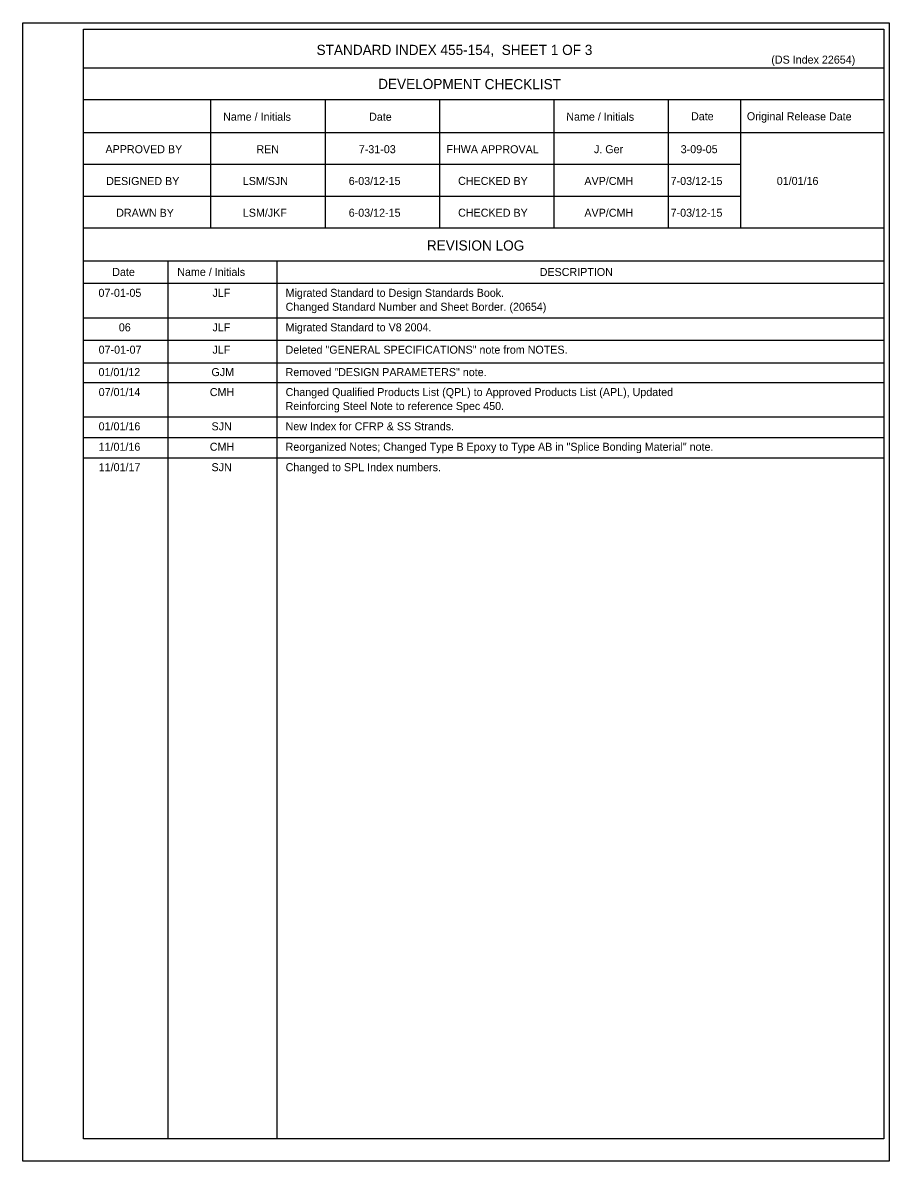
# Model space of a CAD drawing. Extents: x 120517.2 to 120592, y 120519.3 to 120603.1.
# Drawn here: x 120570.2 to 120592.01, y 120568.69 to 120597.36 of the extents above; entities that cross this region are included whole.
import ezdxf

# ---------------------------------------------------------------- set-up
doc = ezdxf.new("R2010")
doc.units = 0
for name, color, linetype in [('AdhocPoint_dp', 7, 'Continuous'), ('Border', 7, 'Continuous'), ('PlotBorder_dp', 7, 'Continuous'), ('SheetBorder_dp', 7, 'Continuous')]:
    doc.layers.add(name, color=color, linetype=linetype)

msp = doc.modelspace()

# ---------------------------------------------------------------- linework, layer by layer
at = {"layer": 'Border'}
for p, q in [((120591.874, 120596.217), (120571.727, 120596.217)), ((120591.874, 120595.417), (120571.727, 120595.417)), ((120574.927, 120595.417), (120574.927, 120592.189)), ((120577.807, 120595.417), (120577.807, 120592.189)), ((120580.687, 120595.417), (120580.687, 120592.189)), ((120583.567, 120595.417), (120583.567, 120592.189)), ((120586.447, 120595.417), (120586.447, 120592.189)), ((120588.262, 120595.417), (120588.262, 120592.189)), ((120591.874, 120594.589), (120571.727, 120594.589)), ((120588.262, 120593.789), (120571.727, 120593.789)), ((120588.262, 120592.989), (120571.727, 120592.989)), ((120591.874, 120592.189), (120571.727, 120592.189)), ((120591.874, 120591.361), (120571.727, 120591.361)), ((120573.848, 120591.361), (120573.848, 120569.255)), ((120576.59, 120591.361), (120576.59, 120569.255)), ((120591.874, 120590.797), (120571.727, 120590.797))]:
    msp.add_line(p, q, dxfattribs=at)
msp.add_lwpolyline([(120571.728, 120597.197), (120591.874, 120597.197), (120591.874, 120569.255), (120571.728, 120569.255)], close=True, dxfattribs=at)
at = {"layer": 'PlotBorder_dp'}
for p, q in [((120571.728, 120589.929), (120591.874, 120589.929)), ((120571.728, 120589.365), (120591.874, 120589.365)), ((120571.728, 120588.801), (120591.874, 120588.801)), ((120571.728, 120588.298), (120591.874, 120588.298)), ((120571.728, 120587.436), (120591.874, 120587.436)), ((120571.728, 120586.921), (120591.874, 120586.921)), ((120571.728, 120586.407), (120591.874, 120586.407))]:
    msp.add_line(p, q, dxfattribs=at)
at = {"layer": 'SheetBorder_dp'}
msp.add_line((120570.197, 120568.693), (120570.197, 120568.693), dxfattribs=at)
msp.add_lwpolyline([(120570.197, 120597.36), (120592.01, 120597.36), (120592.01, 120568.693), (120570.197, 120568.693)], close=True, dxfattribs=at)

# ---------------------------------------------------------------- texts
at = {"layer": 'AdhocPoint_dp'}
for s, height, p in [('STANDARD INDEX 455-154,  SHEET 1 OF 3', 0.256, (120577.593, 120596.549)), ('REN', 0.2016, (120576.079, 120594.076)), ('7-31-03', 0.2016, (120578.657, 120594.076)), ('J. Ger', 0.2016, (120584.577, 120594.076)), ('3-09-05', 0.2016, (120586.761, 120594.076)), ('LSM/SJN', 0.2016, (120575.736, 120593.276)), ('6-03/12-15', 0.2016, (120578.403, 120593.276)), ('AVP/CMH', 0.2016, (120584.336, 120593.276)), ('7-03/12-15', 0.2016, (120586.507, 120593.276)), ('01/01/16', 0.2016, (120589.179, 120593.276)), ('LSM/JKF', 0.2016, (120575.738, 120592.476)), ('6-03/12-15', 0.2016, (120578.403, 120592.476)), ('AVP/CMH', 0.2016, (120584.336, 120592.476)), ('7-03/12-15', 0.2016, (120586.507, 120592.476)), ('DESCRIPTION', 0.2016, (120583.211, 120590.984)), ('07-01-05', 0.2016, (120572.103, 120590.459)), ('JLF', 0.2016, (120574.974, 120590.459)), ('Migrated Standard to Design Standards Book.', 0.2016, (120576.814, 120590.459)), ('Changed Standard Number and Sheet Border. (20654)', 0.2016, (120576.814, 120590.108)), ('06', 0.2016, (120572.615, 120589.591)), ('JLF', 0.2016, (120574.974, 120589.591)), ('Migrated Standard to V8 2004.', 0.2016, (120576.814, 120589.591)), ('07-01-07', 0.2016, (120572.107, 120589.027)), ('JLF', 0.2016, (120574.974, 120589.027)), ('Deleted "GENERAL SPECIFICATIONS" note from NOTES.', 0.2016, (120576.814, 120589.027)), ('01/01/12', 0.2016, (120572.104, 120588.463)), ('Removed "DESIGN PARAMETERS" note.', 0.2016, (120576.814, 120588.463)), ('GJM', 0.2016, (120574.947, 120588.463)), ('07/01/14', 0.2016, (120572.108, 120587.96)), ('CMH', 0.2016, (120574.906, 120587.96)), ('Changed Qualified Products List (QPL) to Approved Products List (APL), Updated', 0.2016, (120576.814, 120587.96)), ('Reinforcing Steel Note to reference Spec 450.', 0.2016, (120576.814, 120587.609)), ('01/01/16', 0.2016, (120572.107, 120587.098)), ('SJN', 0.2016, (120574.949, 120587.098)), ('New Index for CFRP & SS Strands.', 0.2016, (120576.814, 120587.098)), ('11/01/16', 0.2016, (120572.107, 120586.583)), ('CMH', 0.2016, (120574.906, 120586.583)), ('Reorganized Notes; Changed Type B Epoxy to Type AB in "Splice Bonding Material" note.', 0.2016, (120576.814, 120586.583)), ('11/01/17', 0.2016, (120572.109, 120586.069)), ('SJN', 0.2016, (120574.949, 120586.069)), ('Changed to SPL Index numbers.', 0.2016, (120576.814, 120586.069))]:
    msp.add_text(s, height=height, dxfattribs=at).set_placement(p)
for s, height, p in [('DEVELOPMENT CHECKLIST', 0.256, (120579.143, 120595.694)), ('Name / Initials', 0.2016, (120575.24, 120594.896)), ('Date', 0.2016, (120578.915, 120594.894)), ('Name / Initials', 0.2016, (120583.88, 120594.896)), ('Date', 0.2016, (120587.02, 120594.906)), ('Original Release Date', 0.2016, (120588.426, 120594.906)), ('APPROVED BY', 0.2016, (120572.279, 120594.078)), ('FHWA APPROVAL', 0.2016, (120580.863, 120594.078)), ('DESIGNED BY', 0.2016, (120572.296, 120593.276)), ('CHECKED BY', 0.2016, (120581.157, 120593.278)), ('DRAWN BY', 0.2016, (120572.549, 120592.476)), ('CHECKED BY', 0.2016, (120581.157, 120592.478)), ('REVISION LOG', 0.256, (120580.369, 120591.628)), ('Date', 0.2016, (120572.45, 120590.985)), ('Name / Initials', 0.2016, (120574.086, 120590.987))]:
    msp.add_text(s, height=height, rotation=359.8756, dxfattribs=at).set_placement(p)
at = {"layer": 'PlotBorder_dp'}
msp.add_text('(DS Index 22654)', height=0.2016, dxfattribs=at).set_placement((120589.042, 120596.331))

doc.saveas('drawing.dxf')
